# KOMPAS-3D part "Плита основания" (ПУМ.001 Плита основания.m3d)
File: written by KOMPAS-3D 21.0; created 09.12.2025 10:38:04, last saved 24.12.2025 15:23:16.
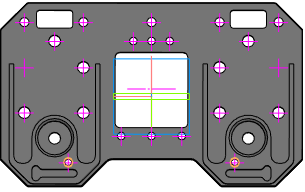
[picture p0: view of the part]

Document properties: Полное имя файла: C:\Users\User\Desktop\ПУ\ПУМ\ПУМ.001 Плита основания.m3d; Автор: User

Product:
- Part/product: Плита основания
    Материал: АМг6  ГОСТ 4784-2019 (density 2650 kg/m3)
    Масса: 0.21633
    Форматы листов документа: 2xA4@4~2

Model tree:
1. Эскиз:1
2. Элемент выдавливания:1
     Расстояние 1 = 4
3. Скругление:1  (with: Элемент выдавливания:1)
     Радиус = 2
4. Скругление:2  (with: Элемент выдавливания:1)
     Радиус = 5
5. Фаска:1  (with: Элемент выдавливания:1)
     Угол = 45; Длина 1 = 0.5; Длина 2 = 0.5
6. Эскиз:2  (with: Элемент выдавливания:1, Фаска:1)
7. Эскиз:3  (with: Элемент выдавливания:1, Фаска:1)  (labels: Основание 1)
8. Элемент выдавливания:2
     Расстояние 2 = 10
9. Скругление:3  (with: Элемент выдавливания:2)
     Радиус = 2
10. Эскиз:4  (with: Элемент выдавливания:1, Элемент выдавливания:5, Элемент выдавливания:7, Элемент выдавливания:8)  (labels: Основание 1)
11. Элемент выдавливания:3
     Расстояние 2 = 10
12. Эскиз:5  (with: Элемент выдавливания:1, Элемент выдавливания:2, Фаска:1)
13. Элемент выдавливания:4  (with: Элемент выдавливания:1)
     Толщина стенки 1 = 2; Расстояние 1 = 8
14. Элемент выдавливания:6  (with: Элемент выдавливания:4)
     Расстояние 2 = 10
15. Скругление:4  (with: Элемент выдавливания:4)
     Радиус = 5
16. Фаска:3  (with: Элемент выдавливания:4)
     Угол = 45; Длина 1 = 1.5; Длина 2 = 1.5
17. Эскиз:6  (with: Элемент выдавливания:4, Фаска:3)
18. Элемент выдавливания:7
     Расстояние 2 = 4
19. Зеркальный массив:3
20. Экземпляр ( 1 )
21. Экземпляр ( 2 )  (with: Элемент выдавливания:4, Фаска:3, Элемент выдавливания:7, Элемент выдавливания:6, Скругление:4)
22. Эскиз:8  (with: Элемент выдавливания:1, Отверстие:1, Фаска:1)
23. Отверстие:1 Блок платы М5 потай  (with: Элемент выдавливания:1, Фаска:1)
     Глубина выреза = 7; Диаметр отверстия = 5.2; Угол конуса дна = 118; Расстояние 1 = 96; Расстояние 2 = 26.7236; Диаметр зенковки = 10; Глубина зенковки = 2.8; Угол зенковки = 81.2026
24. Крепление блока платы м5
25. Экземпляр ( 3 )
26. Отверстие:1  (with: Эскиз:8)
27. Экземпляр ( 4 )  (with: Отверстие:1, Эскиз:8, Экземпляр ( 2 ), Экземпляр ( 1 ))
28. Экземпляр ( 5 )  (with: Отверстие:1, Эскиз:8)
29. Отверстие:2 Дренаж  (with: Элемент выдавливания:1, Фаска:1)
     Глубина выреза = 5; Диаметр отверстия = 8; Угол конуса дна = 118; Расстояние 1 = 96; Расстояние 2 = 80.4637
30. Отверстие:4  (with: Элемент выдавливания:1, Фаска:1)  (labels: M6)
     Глубина выреза = 13; Диаметр отверстия = 4.91747; Угол конуса дна = 118; Расстояние 1 = 15.5; Расстояние 2 = 17.1777
31. M6  (with: Элемент выдавливания:1, Элемент выдавливания:4)  (labels: cil0_24705-2004 coarse)
     Длина резьбы = 8; Шаг резьбы = 1; Номинальный диаметр резьбы = 6
32. Отверстие:5  (with: Элемент выдавливания:1, Фаска:1, M6, Элемент выдавливания:4)  (labels: M6; cil0_24705-2004 coarse)
     Глубина выреза = 13; Диаметр отверстия = 4.91747; Угол конуса дна = 118; Расстояние 1 = 15.5; Расстояние 2 = -60.6041; Длина резьбы = 8; Шаг резьбы = 1; Номинальный диаметр резьбы = 6
33. Макро:1
34. Отверстие:7  (with: Элемент выдавливания:1, Фаска:1)
     Глубина выреза = 40; Диаметр отверстия = 6.2; Угол конуса дна = 118; Расстояние 1 = 108.5; Расстояние 2 = 103.445; Диаметр зенковки = 12; Глубина зенковки = 3.3; Угол зенковки = 82.6172
35. Массив крепление бурта м6  (with: Экземпляр ( 2 ), Отверстие:7, Эскиз:8, Экземпляр ( 4 ), Экземпляр ( 3 ), Экземпляр ( 1 ))
36. Массив дренаж  (with: Экземпляр ( 2 ))
37. Отверстие:2  (with: Эскиз:8)
38. Экземпляр ( 6 )  (with: Отверстие:2, Эскиз:8, Экземпляр ( 4 ))
39. Экземпляр ( 8 )  (with: Отверстие:2, Эскиз:8)
40. Экземпляр ( 7 )  (with: Отверстие:2, Эскиз:8, Экземпляр ( 5 ), Экземпляр ( 3 ))
41. Эскиз:9  (with: Элемент выдавливания:1)
42. Элемент выдавливания:8  (labels: АМг6  ГОСТ 4784-2019)
     Расстояние 2 = 1

Expressions: v847*2
Referenced files in C:\Users\User\Desktop\ПУ\ПУМ\: ПУМ.000.00 Сборка.a3d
